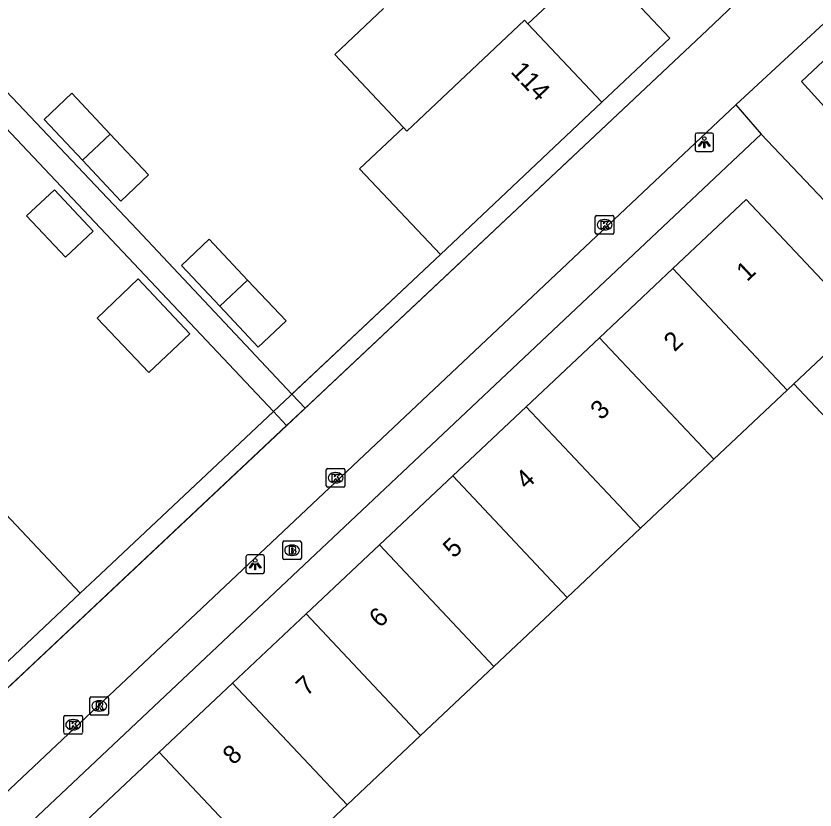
# Model space of a CAD drawing. Extents: x 162542 to 163144, y 380786 to 381511.
# Drawn here: x 162825.34 to 162868.39, y 381245.64 to 381288.43 of the extents above; entities that cross this region are included whole.
import ezdxf

# ---------------------------------------------------------------- set-up
doc = ezdxf.new("R2010")
doc.units = 0
for name, color, linetype in [('IMGEO_Brandkraan', 7, 'Continuous'), ('IMGEO_Hek', 7, 'Continuous'), ('IMGEO_Kolk', 7, 'Continuous'), ('IMGEO_Lichtpunt', 7, 'Continuous'), ('IMGEO_Muur', 7, 'Continuous'), ('IMGEO_Pand', 7, 'Continuous'), ('IMGEO_Pand_nummerreeks', 7, 'Continuous'), ('IMGEO_Rioolput', 7, 'Continuous'), ('IMGEO_Voetpad_open', 7, 'Continuous')]:
    doc.layers.add(name, color=color, linetype=linetype)

msp = doc.modelspace()

# ---------------------------------------------------------------- linework, layer by layer
at = {"layer": 'IMGEO_Brandkraan'}
for p, q in [((162839.717, 381259.21), (162839.717, 381260.062)), ((162839.792, 381260.136), (162840.644, 381260.136)), ((162840.205, 381259.916), (162840.23, 381259.916)), ((162840.718, 381260.062), (162840.718, 381259.21)), ((162840.228, 381259.356), (162840.203, 381259.356)), ((162840.644, 381259.136), (162839.792, 381259.136))]:
    msp.add_line(p, q, dxfattribs=at)
for points in [[(162839.717, 381259.21), (162839.717, 381260.062)], [(162839.792, 381260.136), (162840.644, 381260.136)], [(162840.065, 381259.836), (162840.065, 381259.436), (162840.278, 381259.436)], [(162840.296, 381259.836), (162840.065, 381259.836)], [(162840.244, 381259.755), (162840.19, 381259.755), (162840.19, 381259.679)], [(162840.718, 381260.062), (162840.718, 381259.21)], [(162840.19, 381259.679), (162840.243, 381259.679)], [(162840.252, 381259.603), (162840.19, 381259.603), (162840.19, 381259.522)], [(162840.19, 381259.522), (162840.252, 381259.522)], [(162840.644, 381259.136), (162839.792, 381259.136)]]:
    msp.add_lwpolyline(points, dxfattribs=at)
for centre, radius, start, end in [((162839.794, 381260.06), 0.0765, 91.552, 178.448), ((162839.794, 381260.06), 0.0765, 91.552, 178.448), ((162840.245, 381259.717), 0.0379, 267.8285, 90.9355), ((162840.3, 381259.691), 0.145, 59.4692, 91.5367), ((162840.325, 381259.738), 0.0922, 285.5137, 58.1501), ((162840.642, 381260.06), 0.0765, 1.552, 88.448), ((162840.642, 381260.06), 0.0765, 1.552, 88.448), ((162840.253, 381259.562), 0.0404, 269.8759, 90.5077), ((162840.284, 381259.687), 0.251, 268.6676, 293.5347), ((162840.33, 381259.546), 0.105, 301.3115, 78.989), ((162839.794, 381259.212), 0.0765, 181.552, 268.448), ((162839.794, 381259.212), 0.0765, 181.552, 268.448), ((162840.642, 381259.212), 0.0765, 271.552, 358.448), ((162840.642, 381259.212), 0.0765, 271.552, 358.448)]:
    msp.add_arc(centre, radius, start, end, dxfattribs=at)
for centre, major_axis, ratio, start_param, end_param in [((162840.204, 381259.636), (-0.387, 0.002), 0.722429, 4.712389, 7.853982), ((162840.229, 381259.636), (-0.39, 0.002), 0.717154, 1.570796, 4.712389)]:
    msp.add_ellipse(centre, major_axis=major_axis, ratio=ratio, start_param=start_param, end_param=end_param, dxfattribs=at)
at = {"layer": 'IMGEO_Hek'}
msp.add_lwpolyline([(162758.166, 381200.425), (162772.303, 381209.99), (162785.212, 381218.724), (162787.433, 381220.358), (162797.686, 381227.138), (162801.587, 381230.307), (162862.582, 381287.674)], dxfattribs=at)
at = {"layer": 'IMGEO_Kolk'}
for p, q in [((162856.551, 381276.752), (162856.551, 381277.604)), ((162856.626, 381277.678), (162857.478, 381277.678)), ((162857.039, 381277.458), (162857.064, 381277.458)), ((162857.552, 381277.604), (162857.552, 381276.752)), ((162857.478, 381276.678), (162856.626, 381276.678)), ((162857.062, 381276.898), (162857.037, 381276.898)), ((162842.061, 381263.116), (162842.061, 381263.968)), ((162842.136, 381264.042), (162842.988, 381264.042)), ((162842.549, 381263.822), (162842.574, 381263.822)), ((162843.062, 381263.968), (162843.062, 381263.116)), ((162842.572, 381263.262), (162842.547, 381263.262)), ((162842.988, 381263.042), (162842.136, 381263.042)), ((162827.997, 381250.732), (162828.849, 381250.732)), ((162827.922, 381249.806), (162827.922, 381250.658)), ((162828.41, 381250.512), (162828.435, 381250.512)), ((162828.923, 381250.658), (162828.923, 381249.806)), ((162828.433, 381249.952), (162828.408, 381249.952)), ((162828.849, 381249.732), (162827.997, 381249.732))]:
    msp.add_line(p, q, dxfattribs=at)
for points in [[(162856.551, 381276.752), (162856.551, 381277.604)], [(162856.626, 381277.678), (162857.478, 381277.678)], [(162857.552, 381277.604), (162857.552, 381276.752)], [(162856.872, 381277.378), (162856.995, 381277.378), (162856.995, 381277.227), (162857.125, 381277.378), (162857.289, 381277.378), (162857.143, 381277.227), (162857.296, 381276.978), (162857.144, 381276.978), (162857.059, 381277.142), (162856.995, 381277.075), (162856.995, 381276.978), (162856.872, 381276.978), (162856.872, 381277.378)], [(162857.478, 381276.678), (162856.626, 381276.678)], [(162842.061, 381263.116), (162842.061, 381263.968)], [(162842.136, 381264.042), (162842.988, 381264.042)], [(162842.382, 381263.742), (162842.505, 381263.742), (162842.505, 381263.591), (162842.635, 381263.742), (162842.799, 381263.742), (162842.653, 381263.591), (162842.806, 381263.342), (162842.654, 381263.342), (162842.569, 381263.506), (162842.505, 381263.439), (162842.505, 381263.342), (162842.382, 381263.342), (162842.382, 381263.742)], [(162843.062, 381263.968), (162843.062, 381263.116)], [(162842.988, 381263.042), (162842.136, 381263.042)], [(162827.997, 381250.732), (162828.849, 381250.732)], [(162827.922, 381249.806), (162827.922, 381250.658)], [(162828.243, 381250.432), (162828.366, 381250.432), (162828.366, 381250.281), (162828.496, 381250.432), (162828.66, 381250.432), (162828.514, 381250.281), (162828.667, 381250.032), (162828.515, 381250.032), (162828.43, 381250.196), (162828.366, 381250.129), (162828.366, 381250.032), (162828.243, 381250.032), (162828.243, 381250.432)], [(162828.923, 381250.658), (162828.923, 381249.806)], [(162828.849, 381249.732), (162827.997, 381249.732)]]:
    msp.add_lwpolyline(points, dxfattribs=at)
for centre, start, end in [((162856.628, 381277.602), 91.552, 178.448), ((162856.628, 381277.602), 91.552, 178.448), ((162857.476, 381277.602), 1.552, 88.448), ((162857.476, 381277.602), 1.552, 88.448), ((162856.628, 381276.754), 181.552, 268.448), ((162856.628, 381276.754), 181.552, 268.448), ((162857.476, 381276.754), 271.552, 358.448), ((162857.476, 381276.754), 271.552, 358.448), ((162842.138, 381263.966), 91.552, 178.448), ((162842.138, 381263.966), 91.552, 178.448), ((162842.986, 381263.966), 1.552, 88.448), ((162842.986, 381263.966), 1.552, 88.448), ((162842.138, 381263.118), 181.552, 268.448), ((162842.138, 381263.118), 181.552, 268.448), ((162842.986, 381263.118), 271.552, 358.448), ((162842.986, 381263.118), 271.552, 358.448), ((162827.999, 381250.656), 91.552, 178.448), ((162827.999, 381250.656), 91.552, 178.448), ((162828.847, 381250.656), 1.552, 88.448), ((162828.847, 381250.656), 1.552, 88.448), ((162827.999, 381249.808), 181.552, 268.448), ((162827.999, 381249.808), 181.552, 268.448), ((162828.847, 381249.808), 271.552, 358.448), ((162828.847, 381249.808), 271.552, 358.448)]:
    msp.add_arc(centre, 0.0765, start, end, dxfattribs=at)
for centre, major_axis, ratio, start_param, end_param in [((162857.038, 381277.178), (-0.387, 0.002), 0.722429, 4.712389, 7.853982), ((162857.063, 381277.178), (-0.39, 0.002), 0.717154, 1.570796, 4.712389), ((162842.548, 381263.542), (-0.387, 0.002), 0.722429, 4.712389, 7.853982), ((162842.573, 381263.542), (-0.39, 0.002), 0.717154, 1.570796, 4.712389), ((162828.409, 381250.232), (-0.387, 0.002), 0.722429, 4.712389, 7.853982), ((162828.434, 381250.232), (-0.39, 0.002), 0.717154, 1.570796, 4.712389)]:
    msp.add_ellipse(centre, major_axis=major_axis, ratio=ratio, start_param=start_param, end_param=end_param, dxfattribs=at)
at = {"layer": 'IMGEO_Lichtpunt'}
for p, q in [((162861.928, 381282.03), (162861.928, 381281.223)), ((162861.928, 381282.03), (162861.928, 381281.223)), ((162862.83, 381282.125), (162862.022, 381282.125)), ((162862.83, 381282.125), (162862.022, 381282.125)), ((162862.924, 381281.223), (162862.924, 381282.03)), ((162862.924, 381281.223), (162862.924, 381282.03)), ((162862.022, 381281.129), (162862.83, 381281.129)), ((162862.022, 381281.129), (162862.83, 381281.129)), ((162838.633, 381259.385), (162837.825, 381259.385)), ((162838.633, 381259.385), (162837.825, 381259.385)), ((162837.731, 381259.29), (162837.731, 381258.483)), ((162837.731, 381259.29), (162837.731, 381258.483)), ((162838.727, 381258.483), (162838.727, 381259.29)), ((162838.727, 381258.483), (162838.727, 381259.29)), ((162837.825, 381258.389), (162838.633, 381258.389)), ((162837.825, 381258.389), (162838.633, 381258.389))]:
    msp.add_line(p, q, dxfattribs=at)
for points in [[(162862.302, 381281.694), (162862.341, 381281.666), (162862.153, 381281.404), (162862.115, 381281.431), (162862.302, 381281.694)], [(162862.404, 381281.646), (162862.451, 381281.646), (162862.451, 381281.324), (162862.404, 381281.324), (162862.404, 381281.646)], [(162862.514, 381281.666), (162862.552, 381281.693), (162862.739, 381281.431), (162862.7, 381281.403), (162862.514, 381281.666)], [(162838.105, 381258.954), (162838.144, 381258.926), (162837.956, 381258.664), (162837.918, 381258.691), (162838.105, 381258.954)], [(162838.207, 381258.906), (162838.254, 381258.906), (162838.254, 381258.584), (162838.207, 381258.584), (162838.207, 381258.906)], [(162838.317, 381258.926), (162838.355, 381258.953), (162838.542, 381258.691), (162838.503, 381258.663), (162838.317, 381258.926)]]:
    msp.add_lwpolyline(points, dxfattribs=at)
for centre in [(162862.427, 381281.828), (162838.23, 381259.088)]:
    msp.add_circle(centre, 0.0994, dxfattribs=at)
for centre, start, end in [((162862.022, 381282.03), 90, 180), ((162862.022, 381282.03), 90, 180), ((162862.83, 381282.03), 0, 90), ((162862.83, 381282.03), 0, 90), ((162862.022, 381281.223), 180, 270), ((162862.022, 381281.223), 180, 270), ((162862.83, 381281.223), 270, 0), ((162862.83, 381281.223), 270, 360), ((162837.825, 381259.29), 90, 180), ((162837.825, 381259.29), 90, 180), ((162838.633, 381259.29), 0, 90), ((162838.633, 381259.29), 0, 90), ((162837.825, 381258.483), 180, 270), ((162837.825, 381258.483), 180, 270), ((162838.633, 381258.483), 270, 0), ((162838.633, 381258.483), 270, 360)]:
    msp.add_arc(centre, 0.0946, start, end, dxfattribs=at)
at = {"layer": 'IMGEO_Muur'}
msp.add_lwpolyline([(162848.214, 381275.579), (162829.602, 381258.072), (162828.807, 381257.324)], dxfattribs=at)
at = {"layer": 'IMGEO_Pand'}
for points in [[(162856.594, 381291.461), (162852.926, 381288.007)], [(162846.215, 381282.428), (162842.513, 381286.36), (162845.137, 381288.831)], [(162852.926, 381288.007), (162852.742, 381288.203), (162846.4, 381282.232), (162846.215, 381282.428)], [(162852.926, 381288.007), (162856.908, 381283.784)], [(162828.917, 381280.659), (162826.853, 381282.856), (162828.346, 381284.265), (162830.415, 381282.068)], [(162856.908, 381283.784), (162848.214, 381275.579)], [(162848.214, 381275.579), (162843.842, 381280.193), (162846.215, 381282.428)], [(162830.415, 381282.068), (162832.483, 381279.871), (162830.983, 381278.46), (162828.917, 381280.659)], [(162830.415, 381282.068), (162828.917, 381280.659)], [(162827.408, 381279.058), (162825.905, 381277.657), (162828.006, 381275.428), (162829.505, 381276.829), (162827.408, 381279.058)], [(162860.73, 381274.817), (162864.682, 381278.539), (162869.056, 381273.89), (162871.271, 381275.975), (162873.063, 381274.071), (162870.848, 381271.986), (162867.248, 381268.598)], [(162836.32, 381272.786), (162834.251, 381274.982), (162835.754, 381276.397), (162837.822, 381274.2)], [(162856.777, 381271.093), (162860.73, 381274.817)], [(162860.73, 381274.817), (162866.897, 381268.268)], [(162831.925, 381274.257), (162829.707, 381272.152), (162832.494, 381269.214), (162834.704, 381271.302), (162831.925, 381274.257)], [(162837.822, 381274.2), (162839.891, 381272.003), (162838.389, 381270.589), (162836.32, 381272.786)], [(162836.32, 381272.786), (162837.822, 381274.2)], [(162852.825, 381267.37), (162856.777, 381271.093)], [(162856.777, 381271.093), (162862.945, 381264.544)], [(162866.897, 381268.268), (162867.248, 381268.598)], [(162867.248, 381268.598), (162872.765, 381262.746), (162874.459, 381260.949), (162880.011, 381255.059)], [(162862.945, 381264.544), (162866.897, 381268.268)], [(162848.872, 381263.648), (162852.825, 381267.37)], [(162858.993, 381260.82), (162852.825, 381267.37)], [(162858.993, 381260.82), (162862.945, 381264.544)], [(162844.919, 381259.924), (162848.872, 381263.648)], [(162855.041, 381257.096), (162848.872, 381263.648)], [(162828.807, 381257.324), (162824.778, 381261.603)], [(162855.041, 381257.096), (162858.993, 381260.82)], [(162840.967, 381256.202), (162844.919, 381259.924)], [(162844.919, 381259.924), (162851.089, 381253.373)], [(162818.793, 381247.896), (162828.807, 381257.324)], [(162851.089, 381253.373), (162855.041, 381257.096)], [(162837.014, 381252.478), (162840.967, 381256.202)], [(162847.137, 381249.649), (162840.967, 381256.202)], [(162847.137, 381249.649), (162851.089, 381253.373)], [(162833.061, 381248.755), (162837.014, 381252.478)], [(162843.185, 381245.925), (162837.014, 381252.478)], [(162843.185, 381245.925), (162847.137, 381249.649)], [(162829.109, 381245.032), (162833.061, 381248.755)], [(162839.233, 381242.201), (162833.061, 381248.755)], [(162839.233, 381242.201), (162843.185, 381245.925)]]:
    msp.add_lwpolyline(points, dxfattribs=at)
at = {"layer": 'IMGEO_Rioolput'}
for p, q in [((162829.326, 381250.82), (162829.326, 381251.672)), ((162829.401, 381251.746), (162830.253, 381251.746)), ((162830.327, 381251.672), (162830.327, 381250.82)), ((162829.814, 381251.526), (162829.839, 381251.526)), ((162830.253, 381250.746), (162829.401, 381250.746)), ((162829.837, 381250.966), (162829.812, 381250.966))]:
    msp.add_line(p, q, dxfattribs=at)
for points in [[(162829.326, 381250.82), (162829.326, 381251.672)], [(162829.401, 381251.746), (162830.253, 381251.746)], [(162830.327, 381251.672), (162830.327, 381250.82)], [(162829.915, 381251.444), (162829.663, 381251.446), (162829.663, 381251.046)], [(162829.663, 381251.046), (162829.787, 381251.046), (162829.787, 381251.208), (162829.798, 381251.208)], [(162829.841, 381251.365), (162829.787, 381251.365), (162829.787, 381251.284)], [(162829.787, 381251.284), (162829.839, 381251.284)], [(162829.845, 381251.179), (162829.916, 381251.046), (162830.056, 381251.046), (162829.991, 381251.172)], [(162830.253, 381250.746), (162829.401, 381250.746)]]:
    msp.add_lwpolyline(points, dxfattribs=at)
for centre, radius, start, end in [((162829.403, 381251.67), 0.0765, 91.552, 178.448), ((162829.403, 381251.67), 0.0765, 91.552, 178.448), ((162830.251, 381251.67), 0.0765, 1.552, 88.448), ((162830.251, 381251.67), 0.0765, 1.552, 88.448), ((162829.797, 381251.155), 0.0533, 26.0293, 88.6989), ((162829.823, 381251.473), 0.19, 274.7715, 282.9687), ((162829.847, 381251.269), 0.0964, 77.0061, 93.1865), ((162829.861, 381251.326), 0.0378, 276.6634, 79.6772), ((162829.914, 381251.334), 0.109, 350.3612, 89.416), ((162829.912, 381251.334), 0.112, 277.5842, 350.9817), ((162829.896, 381251.119), 0.108, 29.5134, 73.7905), ((162829.403, 381250.822), 0.0765, 181.552, 268.448), ((162829.403, 381250.822), 0.0765, 181.552, 268.448), ((162830.251, 381250.822), 0.0765, 271.552, 358.448), ((162830.251, 381250.822), 0.0765, 271.552, 358.448)]:
    msp.add_arc(centre, radius, start, end, dxfattribs=at)
for centre, major_axis, ratio, start_param, end_param in [((162829.813, 381251.246), (-0.387, 0.002), 0.722429, 4.712389, 7.853982), ((162829.838, 381251.246), (-0.39, 0.002), 0.717154, 1.570796, 4.712389)]:
    msp.add_ellipse(centre, major_axis=major_axis, ratio=ratio, start_param=start_param, end_param=end_param, dxfattribs=at)
at = {"layer": 'IMGEO_Voetpad_open'}
for points in [[(162839.214, 381267.113), (162825.683, 381281.466), (162814.697, 381293.114), (162796.68, 381312.224), (162792.218, 381308.019), (162774.873, 381326.494)], [(162840.913, 381267.294), (162862.582, 381287.674), (162870.795, 381295.515)], [(162817.1, 381292.525), (162831.866, 381276.917), (162840.206, 381268.046)], [(162856.594, 381291.461), (162860.565, 381287.236), (162856.908, 381283.784)], [(162872.439, 381291.347), (162864.115, 381283.64)], [(162873.956, 381284.687), (162870.901, 381287.931), (162867.659, 381284.894), (162870.656, 381281.598)], [(162864.115, 381283.64), (162796.565, 381219.956)], [(162864.115, 381283.64), (162865.48, 381282.064)], [(162806.242, 381226.227), (162865.48, 381282.064)], [(162865.48, 381282.064), (162871.275, 381275.979), (162871.311, 381275.941), (162873.07, 381274.077), (162878.582, 381268.238), (162880.297, 381266.406), (162887.54, 381258.657), (162894.031, 381251.782)], [(162848.214, 381275.579), (162840.206, 381268.046)], [(162840.206, 381268.046), (162840.913, 381267.294)], [(162839.214, 381267.113), (162829.602, 381258.072), (162828.807, 381257.324)], [(162839.922, 381266.362), (162839.214, 381267.113)], [(162840.913, 381267.294), (162839.922, 381266.362)], [(162763.302, 381208.084), (162773.466, 381210.777), (162785.212, 381218.724), (162787.433, 381220.358), (162797.686, 381227.138), (162801.587, 381230.307), (162839.922, 381266.362)]]:
    msp.add_lwpolyline(points, dxfattribs=at)

# ---------------------------------------------------------------- texts
at = {"layer": 'IMGEO_Pand_nummerreeks'}
for s, rotation, p in [('114', 313.3154, (162851.95, 381285.399)), ('1', 43.2927, (162864.73, 381274.085)), ('2', 43.4391, (162860.821, 381270.3)), ('3', 43.7247, (162856.87, 381266.611)), ('4', 43.4469, (162852.843, 381262.872)), ('5', 43.5783, (162848.926, 381259.17)), ('6', 43.3006, (162844.941, 381255.416)), ('7', 43.4546, (162841.006, 381251.734)), ('8', 43.5925, (162837.058, 381248.021))]:
    msp.add_text(s, height=1, rotation=rotation, dxfattribs=at).set_placement(p)

doc.saveas('drawing.dxf')
